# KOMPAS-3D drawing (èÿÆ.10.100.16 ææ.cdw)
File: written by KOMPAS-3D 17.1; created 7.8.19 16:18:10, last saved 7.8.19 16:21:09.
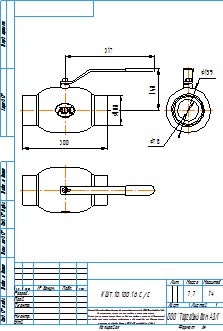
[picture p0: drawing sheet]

Sheet 1: A4, portrait

Title block, sheet 1: name: КШТ.10.100.16 С/С; material: Сталь 20  ГОСТ 1050-2013; mass: 7,7; sheets: 1; sheet format: A4; stored path: \\adlc.lan\data\АДЛ_ПКД\3D-модели\ADL production\Шаровые краны БИВАЛ\КШ_Бивал_серия_10\KOMPAS 2D\КШТ.10.100.16 СС.cdw

Views: Вид 1, Проекционный вид 2, Проекционный вид 3
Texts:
  kka
  adl
  Рама для чертежей
  Лит-Масса-Масштаб
  Материал-Предприятие
  Масштаб
  Изм.
  Лист
  № докум.
  Подп.
  Дата
  Лит.
  Разраб.
  Пров.
  Т.контр.
  Листов
  Внимание! Данный продукт является объектом авторского права ООО «Торговый Дом АДЛ».
  Запрещается изменение, копирование, распространение
  (в том числе путем копирования на другие сайты и ресурсы в Интернете)
  или любое иное использование информации и объектов без предварительного
  согласия правообладателя (ООО «Торговый Дом АДЛ»).
  Н.контр.
  Утв.
  ООО "Торговый дом АДЛ"
  Изменение
  Номер документа
  Подпись
  Обозначение документа
  Наименование изделия
  Масса изделия по ГОСТ 2.109-73
  Порядковый номер листа
  Общее количество листов в документе
  Характер работы, выполненной лицом, подписавшим документ
  Наименование или индекс предприятия, выпускающего документ
  Инв. № подл.
  Подп. и дата
  Взам. инв. №
  Инв. № дубл.
  Инвентарный номер подлинника по ГОСТ 2.501-68
  Подпись принявшего подлинник в отдел технической документации
  Инвентарный номер подлинника, взамен которого выпущен данный подлинник
  Инвентарный номер дубликата по ГОСТ 2.502-68
  Подпись принявшего дубликат в отдел технической документации
  Справ. №
  Перв. примен.
  Обозначение документа, взамен или на основании которого выпущен данный документ
  Обозначение документа, в котором впервые записан данный документ
  Подпись лица, копировавшего чертеж
  Обозначение формата листа
  !Рама для чертежа
Dimensions and other numbers on the sheet: 300; 148; 317; 108; 159; 78; 1:4; 1; 7,7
